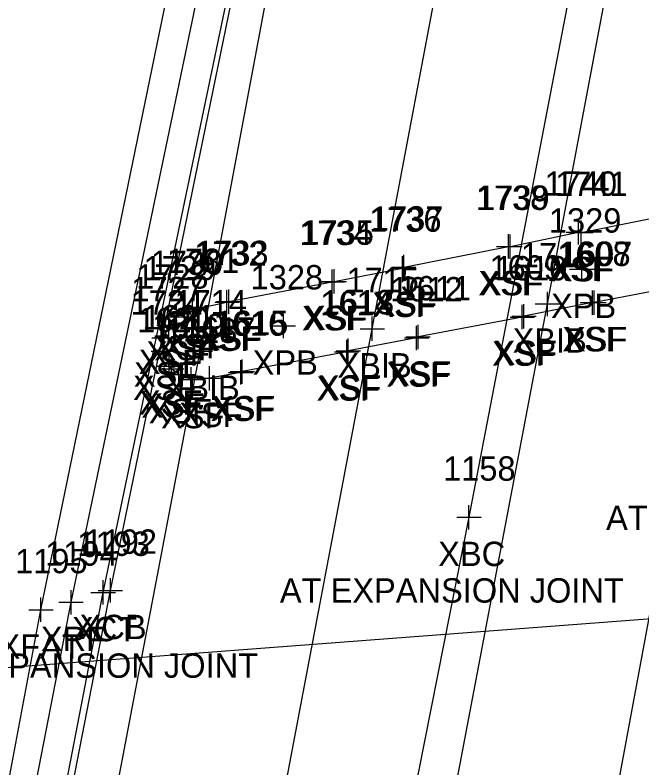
# Model space of a CAD drawing. Extents: x 1683147 to 1683637, y 416837 to 418211.
# Drawn here: x 1683224.43 to 1683250.16, y 417577.53 to 417608.4 of the extents above; entities that cross this region are included whole.
import ezdxf

# ---------------------------------------------------------------- set-up
doc = ezdxf.new("R2010")
doc.units = 0
for name, color, linetype in [('B_A', 7, 'Continuous'), ('B_C', 7, 'Continuous'), ('B_I', 7, 'Continuous'), ('B_TIC', 7, 'Continuous'), ('BB', 7, 'Continuous'), ('BDC', 7, 'Continuous'), ('BDEFAULT', 7, 'Continuous'), ('BELB', 7, 'Continuous'), ('BF', 7, 'Continuous'), ('BR', 7, 'Continuous'), ('LELB', 7, 'Continuous')]:
    doc.layers.add(name, color=color, linetype=linetype)

msp = doc.modelspace()

# ---------------------------------------------------------------- linework, layer by layer
at = {"layer": 'B_TIC'}
for p, q in [((1683247.557, 417599.493), (1683247.632, 417599.493)), ((1683247.662, 417599.481), (1683247.737, 417599.481)), ((1683244.687, 417598.913), (1683244.763, 417598.913)), ((1683244.751, 417598.91), (1683244.827, 417598.91)), ((1683240.335, 417598.017), (1683240.411, 417598.017)), ((1683240.387, 417598.065), (1683240.462, 417598.065)), ((1683247.694, 417597.98), (1683247.769, 417597.98)), ((1683237.448, 417597.469), (1683237.524, 417597.469)), ((1683237.534, 417597.481), (1683237.61, 417597.481)), ((1683233.129, 417596.626), (1683233.205, 417596.626)), ((1683233.207, 417596.65), (1683233.283, 417596.65)), ((1683248.132, 417596.611), (1683248.208, 417596.611)), ((1683248.2, 417596.611), (1683248.275, 417596.611)), ((1683231.723, 417596.327), (1683231.798, 417596.327)), ((1683246.285, 417596.559), (1683246.361, 417596.559)), ((1683231.057, 417596.028), (1683231.133, 417596.028)), ((1683231.39, 417596.246), (1683231.466, 417596.246)), ((1683245.253, 417596.019), (1683245.328, 417596.019)), ((1683245.315, 417596.049), (1683245.39, 417596.049)), ((1683230.746, 417595.685), (1683230.822, 417595.685)), ((1683235.448, 417595.651), (1683235.523, 417595.651)), ((1683239.094, 417595.537), (1683239.17, 417595.537)), ((1683230.551, 417595.167), (1683230.627, 417595.167)), ((1683240.915, 417595.159), (1683240.99, 417595.159)), ((1683240.977, 417595.203), (1683241.052, 417595.203)), ((1683230.517, 417594.619), (1683230.592, 417594.619)), ((1683232.038, 417594.621), (1683232.113, 417594.621)), ((1683238.049, 417594.588), (1683238.125, 417594.588)), ((1683238.107, 417594.632), (1683238.182, 417594.632)), ((1683230.752, 417594.008), (1683230.828, 417594.008)), ((1683230.858, 417593.895), (1683230.934, 417593.895)), ((1683231.155, 417593.657), (1683231.231, 417593.657)), ((1683232.409, 417593.509), (1683232.484, 417593.509)), ((1683233.699, 417593.75), (1683233.775, 417593.75)), ((1683233.759, 417593.779), (1683233.835, 417593.779)), ((1683231.666, 417593.457), (1683231.742, 417593.457)), ((1683243.063, 417587.805), (1683243.139, 417587.805)), ((1683228.049, 417584.722), (1683228.125, 417584.722)), ((1683228.346, 417584.807), (1683228.421, 417584.807)), ((1683226.734, 417584.319), (1683226.809, 417584.319)), ((1683225.498, 417584.011), (1683225.573, 417584.011))]:
    msp.add_line(p, q, dxfattribs=at)
for points in [[(1683247.553, 417598.993), (1683247.553, 417599.993)], [(1683247.658, 417598.981), (1683247.658, 417599.981)], [(1683244.684, 417598.413), (1683244.684, 417599.413)], [(1683244.748, 417598.41), (1683244.748, 417599.41)], [(1683247.053, 417599.493), (1683248.053, 417599.493)], [(1683247.158, 417599.481), (1683248.158, 417599.481)], [(1683244.184, 417598.913), (1683245.184, 417598.913)], [(1683244.248, 417598.91), (1683245.248, 417598.91)], [(1683240.332, 417597.517), (1683240.332, 417598.517)], [(1683240.383, 417597.565), (1683240.383, 417598.565)], [(1683247.691, 417597.48), (1683247.691, 417598.48)], [(1683237.445, 417596.969), (1683237.445, 417597.969)], [(1683237.531, 417596.981), (1683237.531, 417597.981)], [(1683239.832, 417598.017), (1683240.832, 417598.017)], [(1683239.883, 417598.065), (1683240.883, 417598.065)], [(1683247.191, 417597.98), (1683248.191, 417597.98)], [(1683236.945, 417597.469), (1683237.945, 417597.469)], [(1683237.031, 417597.481), (1683238.031, 417597.481)], [(1683233.126, 417596.126), (1683233.126, 417597.126)], [(1683233.204, 417596.15), (1683233.204, 417597.15)], [(1683246.282, 417596.059), (1683246.282, 417597.059)], [(1683248.129, 417596.111), (1683248.129, 417597.111)], [(1683248.196, 417596.111), (1683248.196, 417597.111)], [(1683231.387, 417595.746), (1683231.387, 417596.746)], [(1683231.719, 417595.827), (1683231.719, 417596.827)], [(1683232.626, 417596.626), (1683233.626, 417596.626)], [(1683232.704, 417596.65), (1683233.704, 417596.65)], [(1683247.629, 417596.611), (1683248.629, 417596.611)], [(1683247.696, 417596.611), (1683248.696, 417596.611)], [(1683231.054, 417595.528), (1683231.054, 417596.528)], [(1683231.219, 417596.327), (1683232.219, 417596.327)], [(1683245.249, 417595.519), (1683245.249, 417596.519)], [(1683245.312, 417595.549), (1683245.312, 417596.549)], [(1683245.782, 417596.559), (1683246.782, 417596.559)], [(1683230.554, 417596.028), (1683231.554, 417596.028)], [(1683230.743, 417595.185), (1683230.743, 417596.185)], [(1683230.887, 417596.246), (1683231.887, 417596.246)], [(1683235.444, 417595.151), (1683235.444, 417596.151)], [(1683239.091, 417595.037), (1683239.091, 417596.037)], [(1683244.749, 417596.019), (1683245.749, 417596.019)], [(1683244.812, 417596.049), (1683245.812, 417596.049)], [(1683230.243, 417595.685), (1683231.243, 417595.685)], [(1683230.548, 417594.667), (1683230.548, 417595.667)], [(1683240.911, 417594.659), (1683240.911, 417595.659)], [(1683240.973, 417594.703), (1683240.973, 417595.703)], [(1683234.944, 417595.651), (1683235.944, 417595.651)], [(1683238.591, 417595.537), (1683239.591, 417595.537)], [(1683230.048, 417595.167), (1683231.048, 417595.167)], [(1683230.514, 417594.119), (1683230.514, 417595.119)], [(1683232.034, 417594.121), (1683232.034, 417595.121)], [(1683238.046, 417594.088), (1683238.046, 417595.088)], [(1683238.103, 417594.132), (1683238.103, 417595.132)], [(1683240.411, 417595.159), (1683241.411, 417595.159)], [(1683240.473, 417595.203), (1683241.473, 417595.203)], [(1683230.013, 417594.619), (1683231.014, 417594.619)], [(1683230.749, 417593.508), (1683230.749, 417594.508)], [(1683231.534, 417594.621), (1683232.534, 417594.621)], [(1683237.546, 417594.588), (1683238.546, 417594.588)], [(1683237.603, 417594.632), (1683238.603, 417594.632)], [(1683230.855, 417593.395), (1683230.855, 417594.395)], [(1683231.152, 417593.157), (1683231.152, 417594.157)], [(1683233.696, 417593.25), (1683233.696, 417594.25)], [(1683233.756, 417593.279), (1683233.756, 417594.279)], [(1683230.249, 417594.008), (1683231.249, 417594.008)], [(1683230.355, 417593.895), (1683231.355, 417593.895)], [(1683231.663, 417592.957), (1683231.663, 417593.957)], [(1683232.405, 417593.009), (1683232.405, 417594.009)], [(1683230.652, 417593.657), (1683231.652, 417593.657)], [(1683231.905, 417593.509), (1683232.905, 417593.509)], [(1683233.196, 417593.75), (1683234.196, 417593.75)], [(1683233.256, 417593.779), (1683234.256, 417593.779)], [(1683231.163, 417593.457), (1683232.163, 417593.457)], [(1683243.06, 417587.305), (1683243.06, 417588.305)], [(1683242.56, 417587.805), (1683243.56, 417587.805)], [(1683228.046, 417584.222), (1683228.046, 417585.222)], [(1683228.342, 417584.307), (1683228.342, 417585.307)], [(1683226.73, 417583.819), (1683226.73, 417584.819)], [(1683227.546, 417584.722), (1683228.546, 417584.722)], [(1683227.842, 417584.807), (1683228.842, 417584.807)], [(1683225.494, 417583.511), (1683225.494, 417584.511)], [(1683226.23, 417584.319), (1683227.23, 417584.319)], [(1683224.994, 417584.011), (1683225.994, 417584.011)]]:
    msp.add_lwpolyline(points, dxfattribs=at)
at = {"layer": 'BB'}
for points in [[(1683225.817, 417452.979), (1683235.185, 417501.44), (1683252.981, 417597.315), (1683262.91, 417647.271)], [(1683218.639, 417451.571), (1683227.942, 417499.995), (1683246.282, 417596.559), (1683255.565, 417645.821)], [(1683211.398, 417450.232), (1683220.685, 417498.601), (1683239.091, 417595.537), (1683248.339, 417644.482)], [(1683204.248, 417448.864), (1683213.453, 417497.213), (1683232.034, 417594.621), (1683241.123, 417643.096)]]:
    msp.add_lwpolyline(points, dxfattribs=at)
at = {"layer": 'BDC'}
for points in [[(1683204.26, 417446.59), (1683207.746, 417469.989), (1683213.462, 417505.801), (1683221.311, 417549.93), (1683228.046, 417584.722), (1683234.074, 417613.621), (1683241.065, 417645.18)], [(1683204.523, 417446.635), (1683207.943, 417470.136), (1683213.692, 417505.86), (1683221.542, 417549.946), (1683228.342, 417584.807), (1683234.248, 417613.515), (1683241.392, 417644.923)]]:
    msp.add_lwpolyline(points, dxfattribs=at)
at = {"layer": 'BDEFAULT'}
msp.add_lwpolyline([(1683252.495, 417597.429), (1683248.196, 417596.611), (1683248.129, 417596.611), (1683245.312, 417596.049), (1683245.249, 417596.019), (1683240.973, 417595.203), (1683240.911, 417595.159), (1683238.103, 417594.632), (1683238.046, 417594.588), (1683233.756, 417593.779), (1683233.696, 417593.75), (1683232.405, 417593.509), (1683231.663, 417593.457), (1683231.152, 417593.657), (1683230.855, 417593.895), (1683230.749, 417594.008), (1683230.514, 417594.619), (1683230.548, 417595.167), (1683230.743, 417595.685), (1683231.054, 417596.028), (1683231.387, 417596.246), (1683231.719, 417596.327), (1683233.126, 417596.626), (1683233.204, 417596.65), (1683237.445, 417597.469), (1683237.531, 417597.481), (1683240.332, 417598.017), (1683240.383, 417598.065), (1683244.684, 417598.913), (1683244.748, 417598.91), (1683247.553, 417599.493), (1683247.658, 417599.481), (1683251.874, 417600.335)], dxfattribs=at)
at = {"layer": 'BELB'}
msp.add_lwpolyline([(1683255.821, 417648.166), (1683248.035, 417613.702), (1683243.06, 417587.805), (1683234.781, 417546.02), (1683228.274, 417508.761), (1683222.317, 417473.758), (1683218.863, 417449.537)], dxfattribs=at)
at = {"layer": 'BF'}
msp.add_lwpolyline([(1683201.852, 417446.968), (1683205.241, 417469.957), (1683210.957, 417505.098), (1683219.149, 417550.319), (1683225.494, 417584.011), (1683231.655, 417613.999), (1683238.79, 417645.736)], dxfattribs=at)
at = {"layer": 'BR'}
msp.add_lwpolyline([(1683201.249, 417434.944), (1683203.019, 417446.95), (1683206.413, 417469.882), (1683212.207, 417505.421), (1683220.042, 417550.002), (1683226.73, 417584.319), (1683232.917, 417613.974), (1683239.772, 417645.191), (1683242.155, 417655.448)], dxfattribs=at)
at = {"layer": 'LELB'}
msp.add_lwpolyline([(1683285.091, 417588.015), (1683258.675, 417584.256), (1683207.806, 417580.406)], dxfattribs=at)

# ---------------------------------------------------------------- texts
at = {"layer": 'B_A'}
for s, p in [('XSF', (1683246.313, 417597.493)), ('XSF', (1683246.418, 417597.481)), ('XSF', (1683243.444, 417596.913)), ('XSF', (1683243.508, 417596.91)), ('XSF', (1683239.091, 417596.017)), ('XSF', (1683239.143, 417596.065)), ('XPB', (1683246.427, 417595.98)), ('XSF', (1683236.205, 417595.469)), ('XSF', (1683236.29, 417595.481)), ('XSF', (1683231.964, 417594.65)), ('XSF', (1683231.886, 417594.626)), ('XBIB', (1683244.852, 417594.559)), ('XSF', (1683246.888, 417594.611)), ('XSF', (1683246.956, 417594.611)), ('XSF', (1683229.814, 417594.028)), ('XSF', (1683230.146, 417594.246)), ('XSF', (1683230.479, 417594.327)), ('XSF', (1683244.071, 417594.049)), ('XSF', (1683244.009, 417594.019)), ('XSF', (1683229.503, 417593.685)), ('XPB', (1683234.181, 417593.651)), ('XBIB', (1683237.662, 417593.537)), ('XSF', (1683229.308, 417593.167)), ('XSF', (1683239.671, 417593.159)), ('XSF', (1683239.733, 417593.203)), ('XSF', (1683229.273, 417592.619)), ('XBIB', (1683230.605, 417592.621)), ('XSF', (1683236.806, 417592.588)), ('XSF', (1683236.863, 417592.632)), ('XSF', (1683229.509, 417592.008)), ('XSF', (1683229.615, 417591.895)), ('XSF', (1683229.912, 417591.657)), ('XSF', (1683232.456, 417591.75)), ('XSF', (1683232.516, 417591.779)), ('XSF', (1683230.422, 417591.457)), ('XSF', (1683231.165, 417591.509)), ('XBC', (1683241.796, 417585.805)), ('XCT', (1683226.766, 417582.722)), ('XCB', (1683227.078, 417582.807)), ('XRF', (1683225.49, 417582.319)), ('XFAT', (1683223.75, 417582.011))]:
    msp.add_text(s, height=1, dxfattribs=at).set_placement(p)
at = {"layer": 'B_C'}
for p in [(1683248.687, 417587.285), (1683235.3, 417584.305), (1683220.286, 417581.222)]:
    msp.add_text('AT EXPANSION JOINT', height=1, dxfattribs=at).set_placement(p)
at = {"layer": 'B_I'}
for s, p in [('1740', (1683246.164, 417600.993)), ('1741', (1683246.596, 417600.981)), ('1738', (1683243.337, 417600.413)), ('1739', (1683243.397, 417600.41)), ('1736', (1683238.958, 417599.517)), ('1737', (1683239.037, 417599.565)), ('1329', (1683246.34, 417599.48)), ('1734', (1683236.098, 417598.969)), ('1735', (1683236.184, 417598.981)), ('1732', (1683231.78, 417598.126)), ('1733', (1683231.858, 417598.15)), ('1716', (1683245.191, 417598.059)), ('1608', (1683246.719, 417598.111)), ('1607', (1683246.787, 417598.111)), ('1730', (1683229.997, 417597.746)), ('1731', (1683230.656, 417597.827)), ('1729', (1683229.704, 417597.528)), ('1609', (1683243.898, 417597.549)), ('1610', (1683244.119, 417597.519)), ('1728', (1683229.396, 417597.185)), ('1328', (1683234.098, 417597.151)), ('1715', (1683238.028, 417597.037)), ('1727', (1683229.201, 417596.667)), ('1612', (1683239.825, 417596.659)), ('1611', (1683240.17, 417596.703)), ('1724', (1683229.167, 417596.119)), ('1714', (1683230.971, 417596.121)), ('1614', (1683236.959, 417596.088)), ('1613', (1683237.017, 417596.132)), ('1620', (1683229.442, 417595.395)), ('1621', (1683229.662, 417595.508)), ('1615', (1683232.669, 417595.279)), ('1619', (1683230.061, 417595.157)), ('1618', (1683230.576, 417594.957)), ('1617', (1683231.319, 417595.009)), ('1616', (1683232.582, 417595.25)), ('1158', (1683241.997, 417589.305)), ('1192', (1683227.279, 417586.307)), ('1193', (1683226.983, 417586.222)), ('1194', (1683225.668, 417585.819)), ('1195', (1683224.431, 417585.511))]:
    msp.add_text(s, height=1, dxfattribs=at).set_placement(p)

doc.saveas('drawing.dxf')
